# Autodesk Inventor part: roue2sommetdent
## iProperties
Shininess: 64.0
Length Units: 11269
Angle Units: 11279
Time Units: 11290
Mass Units: 11283
Length Display Precision: 3
Angle Display Precision: 2
Compacted: True
Part Number: roue2sommetdent
Document SubType Name: Modeling
Created: 2004-09
Material: Par défaut
Designer: Administrateur
Density: 1 g/cm^3
Density: 0.0
Volumn: 0.0
Area: 0.0
PropertySet Name: Model Information
Control State: 0
Master: False
Checked Out: False
Author: Administrateur
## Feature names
1. Extrusion1
